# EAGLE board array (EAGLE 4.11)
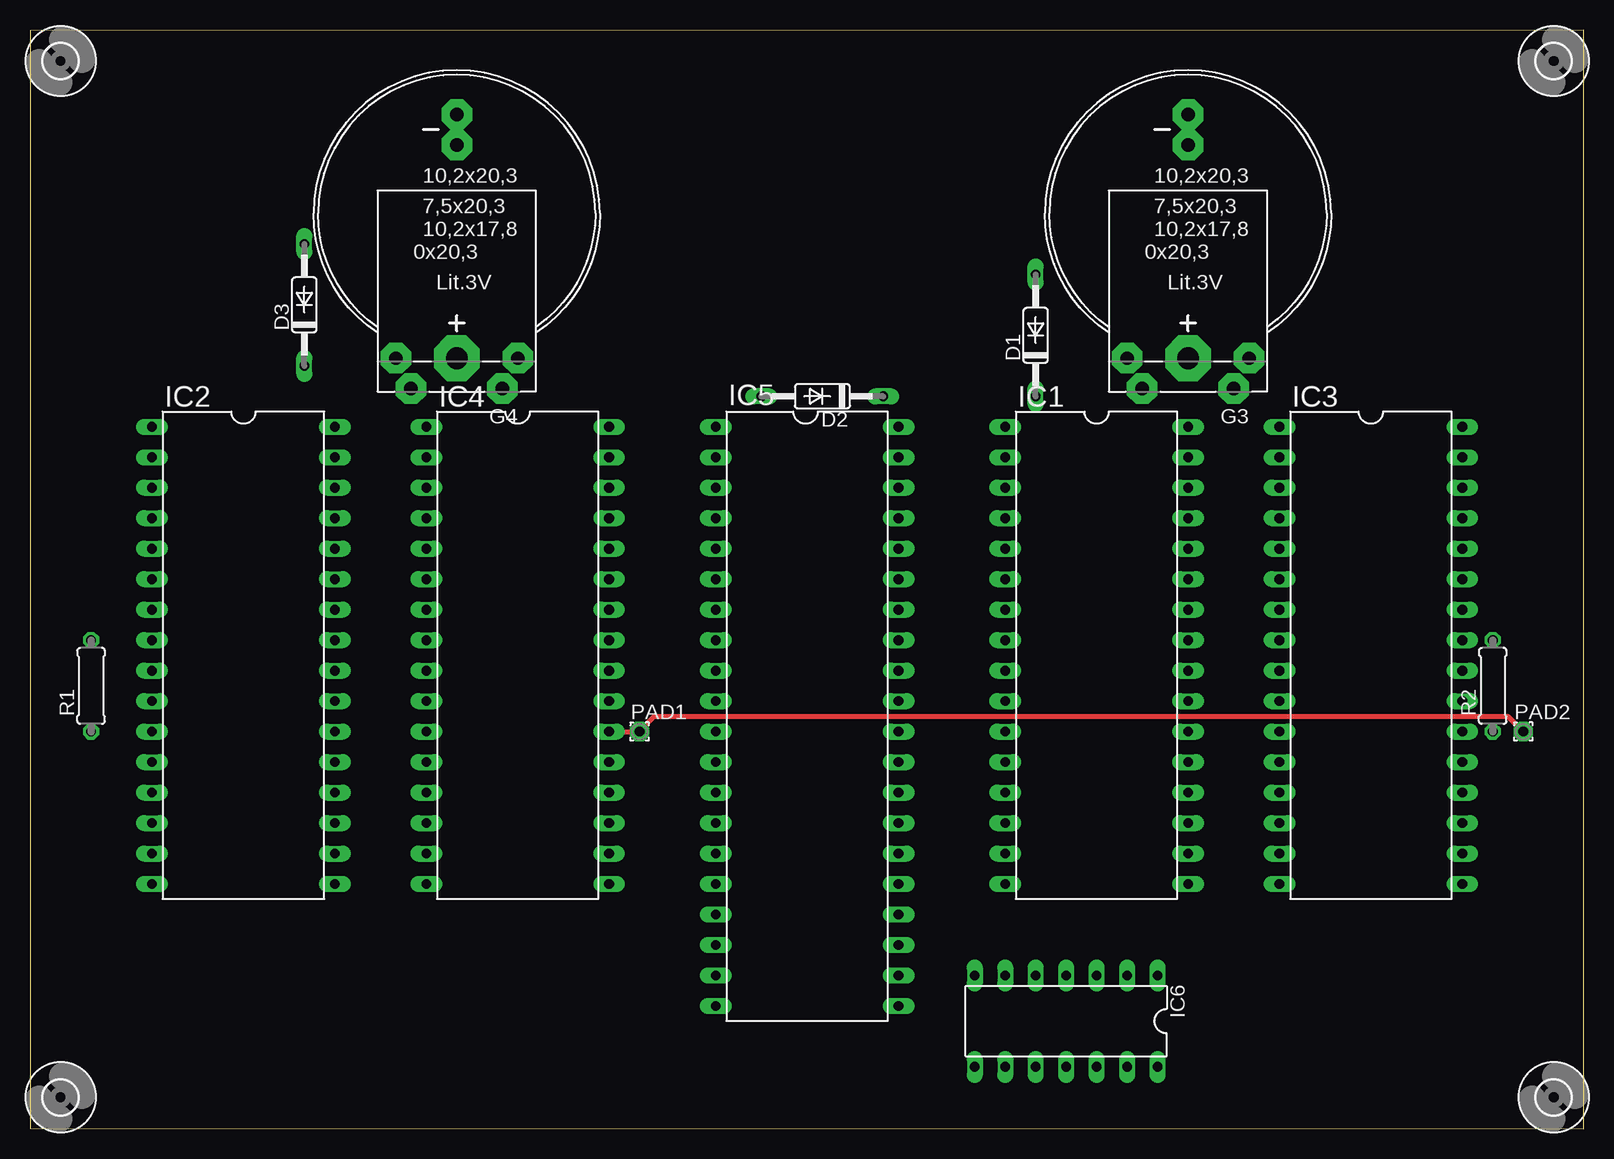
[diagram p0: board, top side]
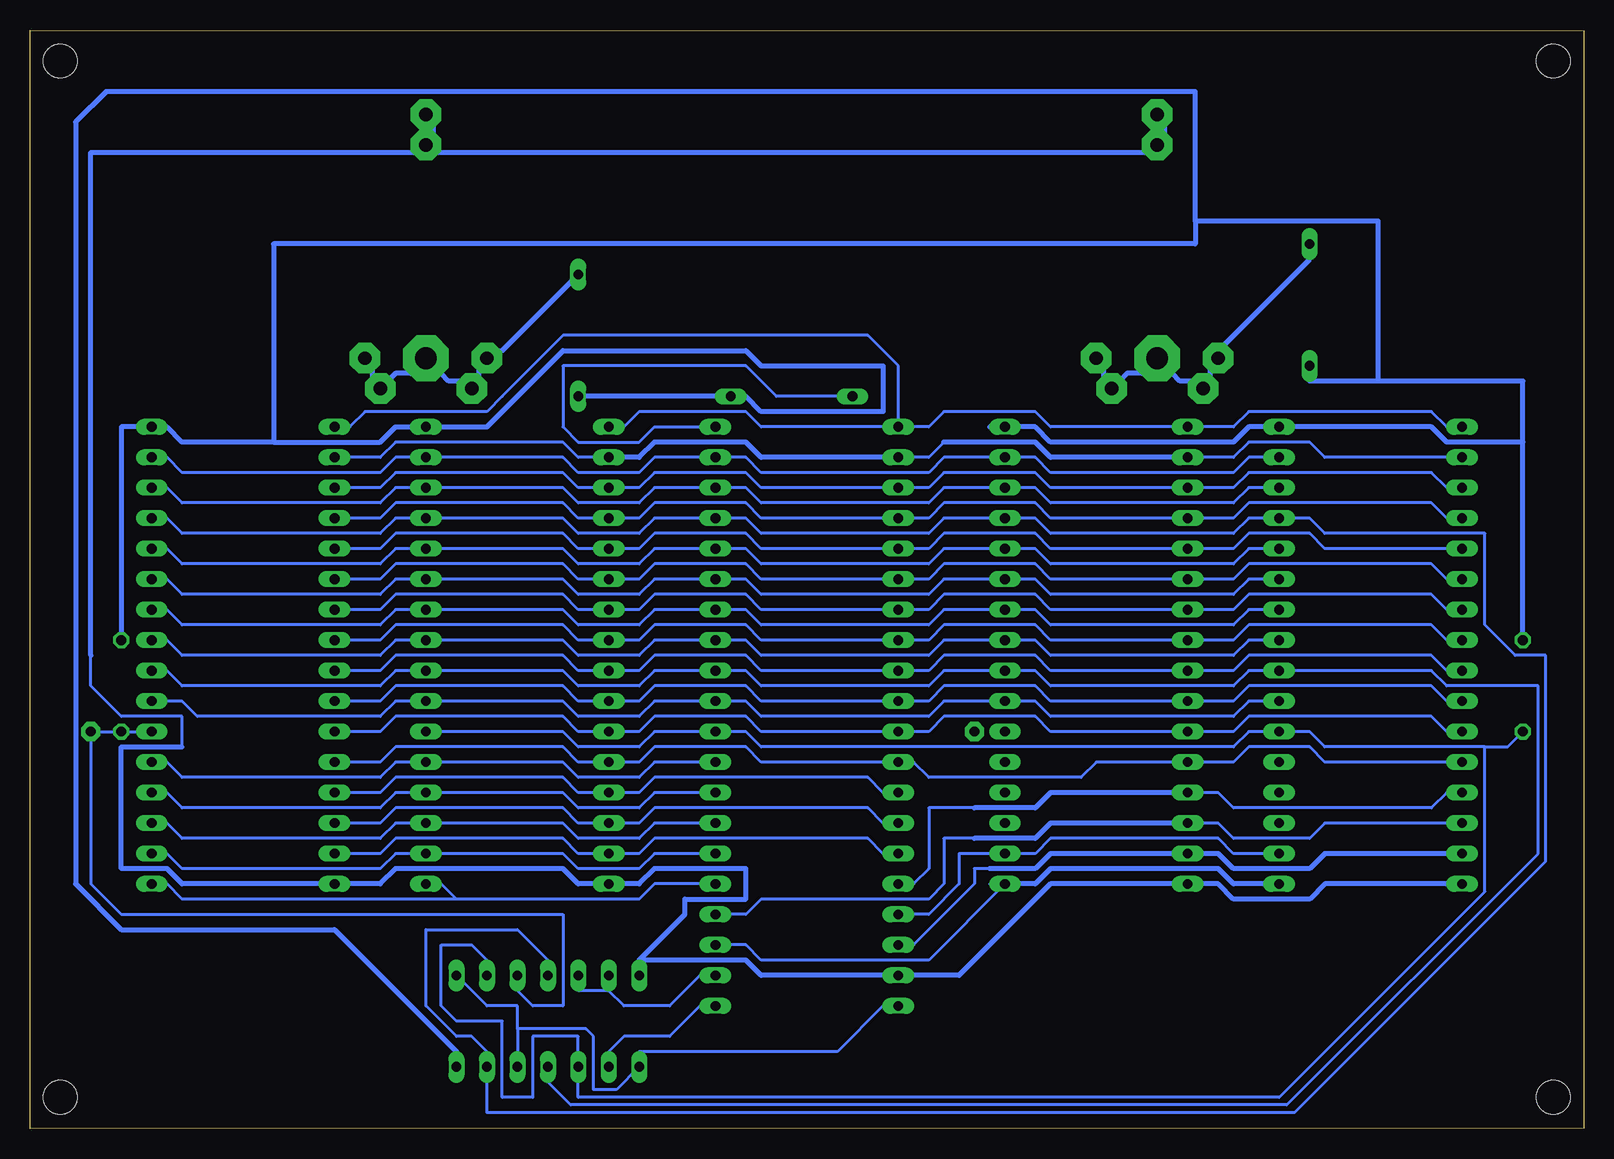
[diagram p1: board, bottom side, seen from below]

Size 129.54 x 91.56 mm. Coordinates in mm from the lower left corner, seen from the top.
Outline: 0,0.05 129.54,0 129.54,91.56 0.03,91.51 0,0.05
Copper layers (1*16): Top 0.035mm / dielectric 1.5mm / Bottom 0.035mm
Design rules "default": minimum track width 10mil, minimum drill 24mil, track to track 8mil, track to pad 8mil, pad to pad 8mil, via to via 8mil, smd to smd 8mil, copper to edge 40mil, drill to drill 8mil, minimum pad ring 10mil, minimum via ring 8mil, stop-mask expansion 4mil, vias tented up to drill 0mil, thermal gap 10mil

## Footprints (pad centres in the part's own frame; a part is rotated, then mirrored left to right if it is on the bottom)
DO35-10 = drill 0.813 long: A 5.08,0; C -5.08,0
B2430UNI = drill 1.118 pad 2.54 octagon: + 3.81,14.605; +@1 -3.81,14.605; +@2 -5.08,12.065; +@3 5.08,12.065; - 0,-5.715; -@1 0,-8.255 | drill 1.803 pad 3.81 octagon: +@4 0,12.065
DIL32 = drill 0.813 long: 1 -19.05,-7.62; 2 -16.51,-7.62; 3 -13.97,-7.62; 4 -11.43,-7.62; 5 -8.89,-7.62; 6 -6.35,-7.62; 7 -3.81,-7.62; 8 -1.27,-7.62; 9 1.27,-7.62; 10 3.81,-7.62; 11 6.35,-7.62; 12 8.89,-7.62; 13 11.43,-7.62; 14 13.97,-7.62; 15 16.51,-7.62; 16 19.05,-7.62; 17 19.05,7.62; 18 16.51,7.62; 19 13.97,7.62; 20 11.43,7.62; 21 8.89,7.62; 22 6.35,7.62; 23 3.81,7.62; 24 1.27,7.62; 25 -1.27,7.62; 26 -3.81,7.62; 27 -6.35,7.62; 28 -8.89,7.62; 29 -11.43,7.62; 30 -13.97,7.62; 31 -16.51,7.62; 32 -19.05,7.62
DIL40 = drill 0.813 long: 1 -24.13,-7.62; 2 -21.59,-7.62; 3 -19.05,-7.62; 4 -16.51,-7.62; 5 -13.97,-7.62; 6 -11.43,-7.62; 7 -8.89,-7.62; 8 -6.35,-7.62; 9 -3.81,-7.62; 10 -1.27,-7.62; 11 1.27,-7.62; 12 3.81,-7.62; 13 6.35,-7.62; 14 8.89,-7.62; 15 11.43,-7.62; 16 13.97,-7.62; 17 16.51,-7.62; 18 19.05,-7.62; 19 21.59,-7.62; 20 24.13,-7.62; 21 24.13,7.62; 22 21.59,7.62; 23 19.05,7.62; 24 16.51,7.62; 25 13.97,7.62; 26 11.43,7.62; 27 8.89,7.62; 28 6.35,7.62; 29 3.81,7.62; 30 1.27,7.62; 31 -1.27,7.62; 32 -3.81,7.62; 33 -6.35,7.62; 34 -8.89,7.62; 35 -11.43,7.62; 36 -13.97,7.62; 37 -16.51,7.62; 38 -19.05,7.62; 39 -21.59,7.62; 40 -24.13,7.62
DIL14 = drill 0.813 long: 1 -7.62,-3.81; 2 -5.08,-3.81; 3 -2.54,-3.81; 4 0,-3.81; 5 2.54,-3.81; 6 5.08,-3.81; 7 7.62,-3.81; 8 7.62,3.81; 9 5.08,3.81; 10 2.54,3.81; 11 0,3.81; 12 -2.54,3.81; 13 -5.08,3.81; 14 -7.62,3.81
1,6/0,8 = drill 0.813 pad 1.6 octagon: 1 0,0
0207/7 = drill 0.813 octagon: 1 -3.81,0; 2 3.81,0
2,8 = hole 2.8: 0,0

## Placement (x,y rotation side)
D1  1N4148  [DO35-10]  83.83,66.11 90 top
D2  1N4148  [DO35-10]  66.05,61.03 180 top
D3  1N4148  [DO35-10]  22.87,68.65 90 top
G3  B2430UNI  [B2430UNI]  96.53,76.27 180 top
G4  B2430UNI  [B2430UNI]  35.57,76.27 180 top
IC1  628512  [DIL32]  88.91,39.44 270 top
IC2  628512  [DIL32]  17.79,39.44 270 top
IC3  628512  [DIL32]  111.77,39.44 270 top
IC4  628512  [DIL32]  40.65,39.44 270 top
IC5  [DIL40]  64.78,34.36 270 top
IC6  4011N  [DIL14]  86.37,8.96 180 top
PAD1  [1,6/0,8]  50.81,33.09 0 top
PAD2  [1,6/0,8]  124.47,33.09 0 top
R1  10meg  [0207/7]  5.09,36.9 90 top
R2  10meg  [0207/7]  121.93,36.9 90 top
U$1  [2,8]  2.55,88.97 0 top
U$2  [2,8]  127.01,88.97 0 top
U$3  [2,8]  127.01,2.61 0 top
U$4  [2,8]  2.55,2.61 0 top

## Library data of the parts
D1-D3 = diode
G3 G4 = battery
IC1-IC4 = memory-hitachi
IC5 = ic-package
IC6 = 40xx
PAD1 PAD2 = wirepad
R1 R2 = rcl
U$1-U$4 = holes

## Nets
+5V: D2.A IC5.40
A0: IC1.12 IC2.12 IC3.12 IC4.12 IC5.12
A1: IC1.11 IC2.11 IC3.11 IC4.11 IC5.11
A2: IC1.10 IC2.10 IC3.10 IC4.10 IC5.10
A3: IC1.9 IC2.9 IC3.9 IC4.9 IC5.9
A4: IC1.8 IC2.8 IC3.8 IC4.8 IC5.8
A5: IC1.7 IC2.7 IC3.7 IC4.7 IC5.7
A6: IC1.6 IC2.6 IC3.6 IC4.6 IC5.6
A7: IC1.5 IC2.5 IC3.5 IC4.5 IC5.5
A8: IC1.27 IC2.27 IC3.27 IC4.27 IC5.35
A9: IC1.26 IC2.26 IC3.26 IC4.26 IC5.34
A10: IC1.23 IC2.23 IC3.23 IC4.23 IC5.31
A11: IC1.25 IC2.25 IC3.25 IC4.25 IC5.33
A12: IC1.4 IC2.4 IC3.4 IC4.4 IC5.4
A13: IC1.28 IC2.28 IC3.28 IC4.28 IC5.36
A14: IC1.3 IC2.3 IC3.3 IC4.3 IC5.3
A15: IC1.31 IC2.31 IC3.31 IC4.31 IC5.39
A16: IC1.2 IC2.2 IC3.2 IC4.2 IC5.2
A17: IC1.30 IC2.30 IC3.30 IC4.30 IC5.38
A18: IC1.1 IC2.1 IC3.1 IC4.1 IC5.1
A19: IC5.21 IC6.9
CS: IC5.20 IC6.1 IC6.8 IC6.12
CS1\: IC1.22 IC2.22 IC5.30 IC6.2 IC6.10 R1.1
CS2\: IC3.22 IC4.22 IC6.3 PAD1.1 PAD2.1 R2.1
D0: IC1.13 IC3.13 IC5.13
D1: IC1.14 IC3.14 IC5.14
D2: IC1.15 IC3.15 IC5.15
D3: IC1.17 IC3.17 IC5.25
D4: IC1.18 IC3.18 IC5.26
D5: IC1.19 IC3.19 IC5.27
D6: IC1.20 IC3.20 IC5.28
D7: IC1.21 IC3.21 IC5.29
D8: IC2.13 IC4.13 IC5.16
D9: IC2.14 IC4.14 IC5.24
D10: IC2.15 IC4.15 IC5.18
D11: IC2.17 IC4.17 IC5.23
GND: G3.- G3.-@1 G4.- G4.-@1 IC1.16 IC2.16 IC3.16 IC4.16 IC5.19 IC6.7
N$1: D1.A G3.+ G3.+@1 G3.+@2 G3.+@3 G3.+@4
N$2: D3.A G4.+ G4.+@1 G4.+@2 G4.+@3 G4.+@4
ODD: IC2.18 IC4.18 IC5.17
OE\: IC1.24 IC2.24 IC3.24 IC4.24 IC5.32 IC6.11
VCC: D1.C D2.C D3.C IC1.32 IC2.32 IC3.32 IC4.32 IC6.14 R1.2 R2.2
WE: IC5.22 IC6.5 IC6.6
WE\: IC1.29 IC2.29 IC3.29 IC4.29 IC5.37 IC6.4 IC6.13

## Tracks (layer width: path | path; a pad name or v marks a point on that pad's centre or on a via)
+5V
  Bottom 0.254: IC5.40 77.48,58.49 78.75,57.22 83.83,57.22 85.1,58.49 85.1,63.57 69.86,63.57 67.32,61.03 D2.A
A0
  Bottom 0.254: IC3.12 100.34,30.55 99.07,31.82 85.1,31.82 83.83,30.55 IC1.12 78.75,30.55 77.48,31.82 69.86,31.82 68.59,30.55 IC5.12 55.89,30.55 54.62,29.28 41.92,29.28 40.65,30.55 IC4.12 29.22,30.55 27.95,31.82 22.87,31.82 21.6,30.55 IC2.12
A1
  Bottom 0.254: IC2.11 11.44,33.09 12.71,34.36 27.95,34.36 29.22,33.09 IC4.11 44.46,33.09 45.73,34.36 53.35,34.36 54.62,33.09 IC5.11 68.59,33.09 69.86,34.36 77.48,34.36 78.75,33.09 IC1.11 83.83,33.09 85.1,34.36 99.07,34.36 100.34,33.09 IC3.11
A2
  Bottom 0.254: IC2.10 11.44,35.63 12.71,36.9 27.95,36.9 29.22,35.63 IC4.10 44.46,35.63 45.73,36.9 53.35,36.9 54.62,35.63 IC5.10 68.59,35.63 69.86,36.9 77.48,36.9 78.75,35.63 IC1.10 83.83,35.63 85.1,36.9 99.07,36.9 100.34,35.63 IC3.10
A3
  Bottom 0.254: IC2.9 11.44,38.17 12.71,39.44 27.95,39.44 29.22,38.17 IC4.9 44.46,38.17 45.73,39.44 53.35,39.44 54.62,38.17 IC5.9 68.59,38.17 69.86,39.44 77.48,39.44 78.75,38.17 IC1.9 83.83,38.17 85.1,39.44 99.07,39.44 100.34,38.17 IC3.9
A4
  Bottom 0.254: IC3.8 100.34,40.71 99.07,41.98 85.1,41.98 83.83,40.71 IC1.8 78.75,40.71 77.48,41.98 69.86,41.98 68.59,40.71 IC5.8 54.62,40.71 53.35,41.98 45.73,41.98 44.46,40.71 IC4.8 29.22,40.71 27.95,41.98 12.71,41.98 11.44,40.71 IC2.8
A5
  Bottom 0.254: IC2.7 11.44,43.25 12.71,44.52 27.95,44.52 29.22,43.25 IC4.7 44.46,43.25 45.73,44.52 53.35,44.52 54.62,43.25 IC5.7 68.59,43.25 69.86,44.52 77.48,44.52 78.75,43.25 IC1.7 83.83,43.25 85.1,44.52 99.07,44.52 100.34,43.25 IC3.7
A6
  Bottom 0.254: IC2.6 11.44,45.79 12.71,47.06 27.95,47.06 29.22,45.79 IC4.6 44.46,45.79 45.73,47.06 53.35,47.06 54.62,45.79 IC5.6 68.59,45.79 69.86,47.06 77.48,47.06 78.75,45.79 IC1.6 83.83,45.79 85.1,47.06 99.07,47.06 100.34,45.79 IC3.6
A7
  Bottom 0.254: IC3.5 100.34,48.33 99.07,49.6 85.1,49.6 83.83,48.33 IC1.5 78.75,48.33 77.48,49.6 69.86,49.6 68.59,48.33 IC5.5 54.62,48.33 53.35,49.6 45.73,49.6 44.46,48.33 IC4.5 29.22,48.33 27.95,49.6 22.87,49.6 21.6,48.33 IC2.5
A8
  Bottom 0.254: IC2.27 27.95,45.79 29.22,44.52 44.46,44.52 45.73,45.79 IC4.27 53.35,45.79 54.62,44.52 68.59,44.52 69.86,45.79 IC5.35 77.48,45.79 78.75,44.52 83.83,44.52 85.1,45.79 IC1.27 99.07,45.79 100.34,44.52 116.85,44.52 118.12,45.79 IC3.27
A9
  Bottom 0.254: IC3.26 118.12,43.25 116.85,41.98 100.34,41.98 99.07,43.25 IC1.26 85.1,43.25 83.83,41.98 78.75,41.98 77.48,43.25 IC5.34 69.86,43.25 68.59,41.98 54.62,41.98 53.35,43.25 IC4.26 45.73,43.25 44.46,41.98 29.22,41.98 27.95,43.25 IC2.26
A10
  Bottom 0.254: IC3.23 116.85,35.63 115.58,34.36 100.34,34.36 99.07,35.63 IC1.23 85.1,35.63 83.83,34.36 78.75,34.36 77.48,35.63 IC5.31 69.86,35.63 68.59,34.36 54.62,34.36 53.35,35.63 IC4.23 45.73,35.63 44.46,34.36 29.22,34.36 27.95,35.63 IC2.23
A11
  Bottom 0.254: IC3.25 118.12,40.71 116.85,39.44 100.34,39.44 99.07,40.71 IC1.25 85.1,40.71 83.83,39.44 78.75,39.44 77.48,40.71 IC5.33 69.86,40.71 68.59,39.44 54.62,39.44 53.35,40.71 IC4.25 45.73,40.71 44.46,39.44 29.22,39.44 27.95,40.71 IC2.25
A12
  Bottom 0.254: IC2.4 11.44,50.87 12.71,52.14 27.95,52.14 29.22,50.87 IC4.4 44.46,50.87 45.73,52.14 53.35,52.14 54.62,50.87 IC5.4 68.59,50.87 69.86,52.14 77.48,52.14 78.75,50.87 IC1.4 83.83,50.87 85.1,52.14 99.07,52.14 100.34,50.87 IC3.4
A13
  Bottom 0.254: IC3.28 118.12,48.33 116.85,47.06 100.34,47.06 99.07,48.33 IC1.28 85.1,48.33 83.83,47.06 78.75,47.06 77.48,48.33 IC5.36 69.86,48.33 68.59,47.06 54.62,47.06 53.35,48.33 IC4.28 45.73,48.33 44.46,47.06 29.22,47.06 27.95,48.33 IC2.28
A14
  Bottom 0.254: IC2.3 11.44,53.41 12.71,54.68 27.95,54.68 29.22,53.41 IC4.3 44.46,53.41 45.73,54.68 53.35,54.68 54.62,53.41 IC5.3 68.59,53.41 69.86,54.68 77.48,54.68 78.75,53.41 IC1.3 83.83,53.41 85.1,54.68 99.07,54.68 100.34,53.41 IC3.3
A15
  Bottom 0.254: IC3.31 118.12,55.95 116.85,54.68 100.34,54.68 99.07,55.95 IC1.31 85.1,55.95 83.83,54.68 78.75,54.68 77.48,55.95 IC5.39 69.86,55.95 68.59,54.68 54.62,54.68 53.35,55.95 IC4.31 45.73,55.95 44.46,54.68 29.22,54.68 27.95,55.95 IC2.31
A16
  Bottom 0.254: IC2.2 21.6,55.95 22.87,57.22 27.95,57.22 29.22,55.95 IC4.2 | IC1.2 83.83,55.95 85.1,57.22 99.07,57.22 100.34,55.95 IC3.2 | 53.35,57.22 54.62,55.95 IC5.2
  Bottom 0.406: 53.35,57.22 45.73,57.22 44.46,55.95 IC4.2 | IC5.2 68.59,55.95 69.86,57.22 77.48,57.22 78.75,55.95 IC1.2
A17
  Bottom 0.254: IC3.30 118.12,53.41 116.85,52.14 100.34,52.14 99.07,53.41 IC1.30 85.1,53.41 83.83,52.14 78.75,52.14 77.48,53.41 IC5.38 69.86,53.41 68.59,52.14 54.62,52.14 53.35,53.41 IC4.30 45.73,53.41 44.46,52.14 29.22,52.14 27.95,53.41 IC2.30
A18
  Bottom 0.254: IC2.1 11.44,58.49 12.71,59.76 27.95,59.76 29.22,58.49 IC4.1 44.46,58.49 45.73,59.76 53.35,59.76 54.62,58.49 IC5.1 | IC5.1 68.59,58.49 69.86,59.76 78.75,59.76 80.02,58.49 IC1.1 | IC5.1 57.16,63.57 59.7,66.11 85.1,66.11 90.18,61.03 91.45,59.76 101.61,59.76 102.88,58.49 | 102.88,58.49 IC3.1 102.88,58.49
A19
  Bottom 0.254: IC6.9 81.29,6.42 80.02,7.69 76.21,7.69 73.67,10.23 IC5.21
CS
  Bottom 0.254: IC5.20 58.43,10.23 62.24,6.42 78.75,6.42 IC6.8 80.66,3.25 82.56,3.25 82.56,7.69 83.2,8.33 88.91,8.33 | 88.91,8.33 88.91,10.23 91.45,10.23 IC6.1 | 88.91,8.33 IC6.12
CS1\
  Bottom 0.254: IC6.2 91.45,14.04 92.72,15.31 95.26,15.31 95.26,10.23 93.99,8.96 90.18,8.96 90.18,2.61 87.64,2.61 87.64,7.69 83.83,7.69 IC6.10 83.83,2.61 25.41,2.61 8.27,19.76 8.27,31.82 | R1.1 6.36,31.82 8.27,31.82 | 8.27,31.82 21.6,31.82 22.87,33.09 IC2.22 27.95,33.09 29.22,31.82 68.59,31.82 69.86,33.09 IC5.30 77.48,33.09 78.75,31.82 83.83,31.82 85.1,33.09 IC1.22
CS2\
  Top 0.406: IC4.22 PAD1.1 52.08,34.36 123.2,34.36 PAD2.1
  Bottom 0.254: IC6.3 88.91,11.5 87.64,10.23 85.1,10.23 85.1,17.85 121.93,17.85 124.47,20.39 PAD2.1 R2.1 IC3.22
D0
  Bottom 0.254: IC5.13 58.43,28.01 59.7,29.28 77.48,29.28 78.75,28.01 IC1.13 83.83,28.01 85.1,29.28 99.07,29.28 100.34,28.01 IC3.13
D1
  Bottom 0.254: IC5.14 58.43,25.47 59.7,26.74 77.48,26.74 78.75,25.47 IC1.14 83.83,25.47 85.1,26.74 99.07,26.74 100.34,25.47 IC3.14
D2
  Bottom 0.254: IC5.15 58.43,22.93 59.7,24.2 77.48,24.2 78.75,22.93 IC1.15 83.83,22.93 85.1,24.2 99.07,24.2 100.34,22.93 IC3.15
D3
  Bottom 0.254: 93.99,19.12 78.75,19.12 77.48,20.39 IC5.25 | 93.99,19.12 95.26,20.39 IC1.17 | 93.99,19.12 116.85,19.12 118.12,20.39 IC3.17
D4
  Bottom 0.254: IC5.26 77.48,22.93 78.75,21.66 83.83,21.66 85.1,22.93 IC1.18 99.07,22.93 100.34,21.66 116.85,21.66 118.12,22.93 IC3.18
D5
  Bottom 0.254: IC5.27 77.48,25.47 78.75,24.2 83.83,24.2 85.1,25.47 IC1.19 99.07,25.47 100.34,24.2 116.85,24.2 118.12,25.47 IC3.19
D6
  Bottom 0.254: IC5.28 77.48,28.01 78.75,26.74 83.83,26.74 85.1,28.01 IC1.20 99.07,28.01 100.34,26.74 116.85,26.74 118.12,28.01 IC3.20
D7
  Bottom 0.254: IC5.29 77.48,30.55 78.75,29.28 83.83,29.28 85.1,30.55 IC1.21 99.07,30.55 100.34,29.28 116.85,29.28 118.12,30.55 IC3.21
D8
  Bottom 0.254: IC2.13 11.44,28.01 12.71,26.74 29.22,26.74 30.49,28.01 IC4.13 | 50.81,26.74 54.62,26.74 54.62,21.66 55.89,20.39 IC5.16
  Bottom 0.406: IC4.13 44.46,28.01 45.73,26.74 50.81,26.74
D9
  Bottom 0.254: IC2.14 21.6,25.47 22.87,24.2 29.22,24.2 30.49,25.47 IC4.14 | 50.81,24.2 53.35,24.2 53.35,20.39 54.62,19.12 68.59,19.12 69.86,17.85 IC5.24
  Bottom 0.406: IC4.14 44.46,25.47 45.73,24.2 50.81,24.2
D10
  Bottom 0.254: 49.54,21.66 50.81,21.66 50.81,20.39 55.89,15.31 IC5.18
  Bottom 0.406: IC2.15 21.6,22.93 22.87,21.66 29.22,21.66 30.49,22.93 IC4.15 44.46,22.93 45.73,21.66 49.54,21.66
D11
  Bottom 0.254: IC5.23 69.86,15.31 68.59,14.04 54.62,14.04 IC4.17 49.54,20.39 | IC2.17 26.68,20.39
  Bottom 0.406: 26.68,20.39 29.22,20.39 30.49,21.66 44.46,21.66 45.73,20.39 IC4.17
GND
  Bottom 0.254: 35.57,81.35 95.9,81.35 96.53,81.35 | IC2.16 11.44,20.39 | 116.85,31.82 116.85,34.36 121.93,34.36 124.47,36.9 124.47,39.44
  Bottom 0.406: 95.9,81.35 124.47,81.35 124.47,39.44 | 95.9,81.35 35.57,81.35 G4.- 34.94,82.62 34.94,83.89 G4.-@1 | 116.85,31.82 121.93,31.82 121.93,21.66 118.12,21.66 116.85,20.39 IC3.16 100.34,20.39 99.07,21.66 85.1,21.66 83.83,20.39 IC1.16 78.75,20.39 77.48,21.66 69.86,21.66 69.86,19.12 74.94,19.12 74.94,17.85 78.75,14.04 | 11.44,20.39 21.6,20.39 22.87,19.12 29.22,19.12 30.49,20.39 IC4.16 44.46,20.39 52.08,12.77 IC5.19 68.59,12.77 69.86,14.04 78.75,14.04 | 78.75,14.04 IC6.7 | 95.9,81.35 G3.- 95.9,82.62 95.9,83.89 G3.-@1
N$1
  Bottom 0.406: G3.+@2 100.98,63.57 100.98,62.3 G3.+@1 99.71,62.3 99.07,62.94 97.8,62.94 G3.+@4 95.26,62.94 94.63,62.3 93.36,62.3 G3.+ 92.09,62.3 92.09,63.57 G3.+@3 90.82,64.84 90.18,64.84 84.47,70.56 D1.A
N$2
  Bottom 0.406: G4.+@2 40.02,63.57 40.02,62.3 G4.+@1 38.75,62.3 38.11,62.94 36.84,62.94 G4.+@4 34.3,62.94 33.67,62.3 32.4,62.3 G4.+ 31.13,62.3 31.13,63.57 G4.+@3 30.49,64.84 22.87,72.46 D3.A
ODD
  Bottom 0.254: IC2.18 29.22,22.93 30.49,24.2 44.46,24.2 45.73,22.93 IC4.18 52.08,22.93 52.08,20.39 54.62,17.85 IC5.17
OE\
  Bottom 0.254: IC3.24 118.12,38.17 116.85,36.9 100.34,36.9 99.07,38.17 IC1.24 85.1,38.17 83.83,36.9 78.75,36.9 77.48,38.17 IC5.32 69.86,38.17 68.59,36.9 54.62,36.9 53.35,38.17 IC4.24 45.73,38.17 44.46,36.9 29.22,36.9 27.95,38.17 IC2.24 12.71,38.17 11.44,36.9 3.82,36.9 3.82,22.93 24.78,1.98 84.47,1.98 86.37,3.88 IC6.11
VCC
  Bottom 0.254: 47,58.49 IC4.32 49.54,58.49
  Bottom 0.406: 5.09,57.22 5.09,62.3 17.16,62.3 | R1.2 5.09,57.22 | 17.16,62.3 22.87,62.3 D3.C | 5.09,57.22 11.44,57.22 12.71,58.49 IC2.32 27.95,58.49 29.22,57.22 44.46,57.22 45.73,58.49 49.54,58.49 | D1.C D2.C 69.86,61.03 68.59,59.76 58.43,59.76 58.43,63.57 68.59,63.57 69.86,64.84 85.1,64.84 91.45,58.49 IC1.32 99.07,58.49 100.34,57.22 109.23,57.22 | 109.23,57.22 116.85,57.22 118.12,58.49 IC3.32 121.93,58.49 R2.2 | 109.23,57.22 109.23,73.73 32.4,73.73 32.4,75.64 | IC6.14 93.99,6.42 104.15,16.58 121.93,16.58 125.74,20.39 125.74,83.89 123.2,86.43 32.4,86.43 32.4,75.64 | 17.16,62.3 17.16,75.64 32.4,75.64
WE
  Bottom 0.254: 81.29,11.5 83.83,11.5 IC6.5 | 81.29,11.5 80.02,10.23 76.21,10.23 73.67,12.77 IC5.22 | 81.29,11.5 IC6.6
WE\
  Bottom 0.254: IC3.29 118.12,50.87 116.85,49.6 100.34,49.6 99.07,50.87 IC1.29 85.1,50.87 83.83,49.6 78.75,49.6 77.48,50.87 IC5.37 69.86,50.87 68.59,49.6 54.62,49.6 53.35,50.87 IC4.29 45.73,50.87 44.46,49.6 29.22,49.6 27.95,50.87 IC2.29 22.87,50.87 21.6,49.6 8.27,49.6 8.27,41.98 5.73,39.44 3.19,39.44 3.19,22.3 24.14,1.34 91.45,1.34 IC6.13 91.45,6.42 92.72,7.69 93.99,7.69 96.53,10.23 96.53,16.58 88.91,16.58 86.37,14.04 IC6.4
